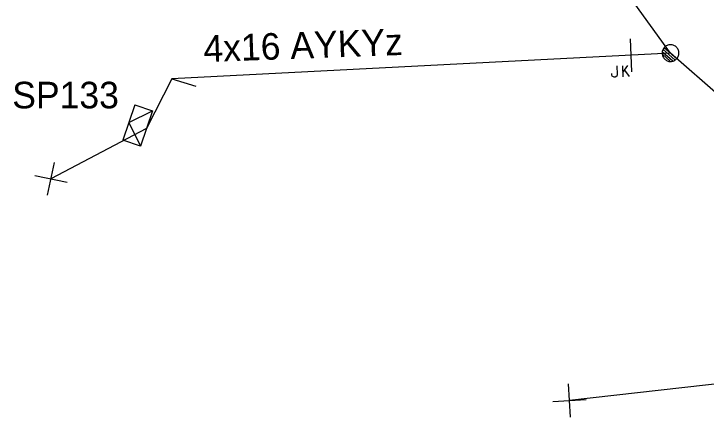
# Model space of a CAD drawing. Extents: x -788458 to -786145, y -1154772 to -1152372.
# Drawn here: x -786438.44 to -786412.38, y -1153461.16 to -1153445.99 of the extents above; entities that cross this region are included whole.
import ezdxf

# ---------------------------------------------------------------- set-up
doc = ezdxf.new("R2010")
doc.units = 0
for name, color, linetype in [('Vrstva 1', 7, 'Continuous'), ('Vrstva 13', 7, 'Continuous'), ('Vrstva 15', 7, 'Continuous'), ('Vrstva 18', 7, 'Continuous'), ('Vrstva 2', 7, 'Continuous'), ('Vrstva 31', 7, 'Continuous'), ('Vrstva 33', 7, 'Continuous'), ('Vrstva 34', 7, 'Continuous'), ('Vrstva 50', 7, 'Continuous'), ('Vrstva 54', 7, 'Continuous'), ('Vrstva 55', 7, 'Continuous'), ('Vrstva 59', 7, 'Continuous'), ('Vrstva 9', 7, 'Continuous')]:
    doc.layers.add(name, color=color, linetype=linetype)

# ---------------------------------------------------------------- blocks, each defined once
blk = doc.blocks.new('NN440')
at = {"layer": 'Vrstva 2'}
for points in [[(0.631, -0.004), (0.627, 0.062), (0.617, 0.127), (0.6, 0.191), (0.577, 0.252), (0.547, 0.311), (0.511, 0.366), (0.469, 0.417), (0.423, 0.464), (0.371, 0.505), (0.316, 0.542), (0.257, 0.571), (0.196, 0.595), (0.132, 0.612), (0.067, 0.622), (0.001, 0.626), (-0.065, 0.622), (-0.13, 0.612), (-0.194, 0.595), (-0.255, 0.571), (-0.314, 0.542), (-0.369, 0.505), (-0.42, 0.464), (-0.467, 0.417), (-0.509, 0.366), (-0.544, 0.311), (-0.574, 0.252), (-0.598, 0.191), (-0.615, 0.127), (-0.626, 0.062), (-0.629, -0.004), (-0.626, -0.07), (-0.615, -0.135), (-0.598, -0.199), (-0.574, -0.26), (-0.544, -0.319), (-0.509, -0.374), (-0.467, -0.426), (-0.42, -0.472), (-0.369, -0.514), (-0.314, -0.55), (-0.255, -0.58), (-0.194, -0.603), (-0.13, -0.62), (-0.065, -0.631), (0.001, -0.634), (0.067, -0.631), (0.132, -0.62), (0.196, -0.603), (0.257, -0.58), (0.316, -0.55), (0.371, -0.514), (0.423, -0.472), (0.469, -0.426), (0.511, -0.374), (0.547, -0.319), (0.577, -0.26), (0.6, -0.199), (0.617, -0.135), (0.627, -0.07), (0.631, -0.004)], [(-0.631, 0), (0.629, 0)], [(-0.601, -0.177), (0.57, -0.177)], [(-0.513, -0.325), (0.501, -0.325)], [(-0.375, -0.473), (0.353, -0.473)]]:
    blk.add_lwpolyline(points, dxfattribs=at)
blk = doc.blocks.new('NN840')
at = {"layer": 'Vrstva 15'}
for points in [[(0.003, 0.619), (0.003, -0.631)], [(-0.538, -0.385), (-0.538, -0.71)], [(-0.332, -0.385), (-0.332, -0.798)], [(-0.332, -0.641), (-0.125, -0.385)], [(-0.745, -0.71), (-0.745, -0.66)], [(-0.73, -0.764), (-0.745, -0.71)], [(-0.657, -0.798), (-0.73, -0.764)], [(-0.558, -0.764), (-0.627, -0.798)], [(-0.538, -0.71), (-0.558, -0.764)], [(-0.263, -0.557), (-0.091, -0.798)], [(-0.627, -0.798), (-0.657, -0.798)]]:
    blk.add_lwpolyline(points, dxfattribs=at)
blk = doc.blocks.new('NN800')
at = {"layer": 'Vrstva 1'}
for points in [[(-0.442, 0.442), (0.442, -0.442)], [(-0.442, -0.442), (0.442, 0.442)]]:
    blk.add_lwpolyline(points, dxfattribs=at)
blk = doc.blocks.new('NN630')
at = {"layer": 'Vrstva 9'}
for points in [[(-0.003, -0.7), (-0.703, 0)], [(-0.703, -0.7), (-0.703, 0), (0.697, 0), (0.697, -0.7)], [(-0.003, -0.7), (0.697, 0)], [(-0.703, -0.7), (0.697, -0.7)]]:
    blk.add_lwpolyline(points, dxfattribs=at)
blk = doc.blocks.new('NN510')
at = {"layer": 'Vrstva 2'}
blk.add_lwpolyline([(0.001, 0.002), (0.001, 0.939)], dxfattribs=at)

msp = doc.modelspace()

# ---------------------------------------------------------------- linework, layer by layer
at = {"layer": 'Vrstva 50'}
msp.add_lwpolyline([(-786402.361, -1153457.407), (-786413.72, -1153447.47), (-786427.01, -1153429.09)], dxfattribs=at)
at = {"layer": 'Vrstva 54'}
msp.add_lwpolyline([(-786413.72, -1153447.47), (-786432.49, -1153448.44), (-786433.45, -1153450.31)], dxfattribs=at)
at = {"layer": 'Vrstva 59'}
for points in [[(-786433.45, -1153450.31), (-786437.04, -1153452.2)], [(-786402.17, -1153458.81), (-786417.525, -1153460.541)]]:
    msp.add_lwpolyline(points, dxfattribs=at)

# ---------------------------------------------------------------- block references
at = {"layer": 'Vrstva 13', "xscale": 0.5000000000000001, "yscale": 0.4999999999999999, "rotation": -41.22922498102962}
msp.add_blockref('NN440', (-786413.72, -1153447.47), dxfattribs=at)
at = {"layer": 'Vrstva 13', "rotation": -106.78118835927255}
msp.add_blockref('NN510', (-786432.49, -1153448.44), dxfattribs=at)
at = {"layer": 'Vrstva 18', "rotation": 2.3983305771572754}
msp.add_blockref('NN840', (-786415.216, -1153447.547), dxfattribs=at)
at = {"layer": 'Vrstva 31', "rotation": -108.96490491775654}
msp.add_blockref('NN630', (-786433.45, -1153450.31), dxfattribs=at)
at = {"layer": 'Vrstva 34'}
for p, rotation in [((-786437.04, -1153452.2), 33.06802504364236), ((-786417.525, -1153460.541), 48.32509443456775)]:
    msp.add_blockref('NN800', p, dxfattribs=dict(at, rotation=rotation))

# ---------------------------------------------------------------- texts
at = {"layer": 'Vrstva 33'}
msp.add_text('SP133', height=1, dxfattribs=at).set_placement((-786438.499, -1153449.55))
at = {"layer": 'Vrstva 55'}
msp.add_text('4x16 AYKYz', height=1, rotation=2.06, dxfattribs=at).set_placement((-786431.285, -1153447.81))

doc.saveas('drawing.dxf')
